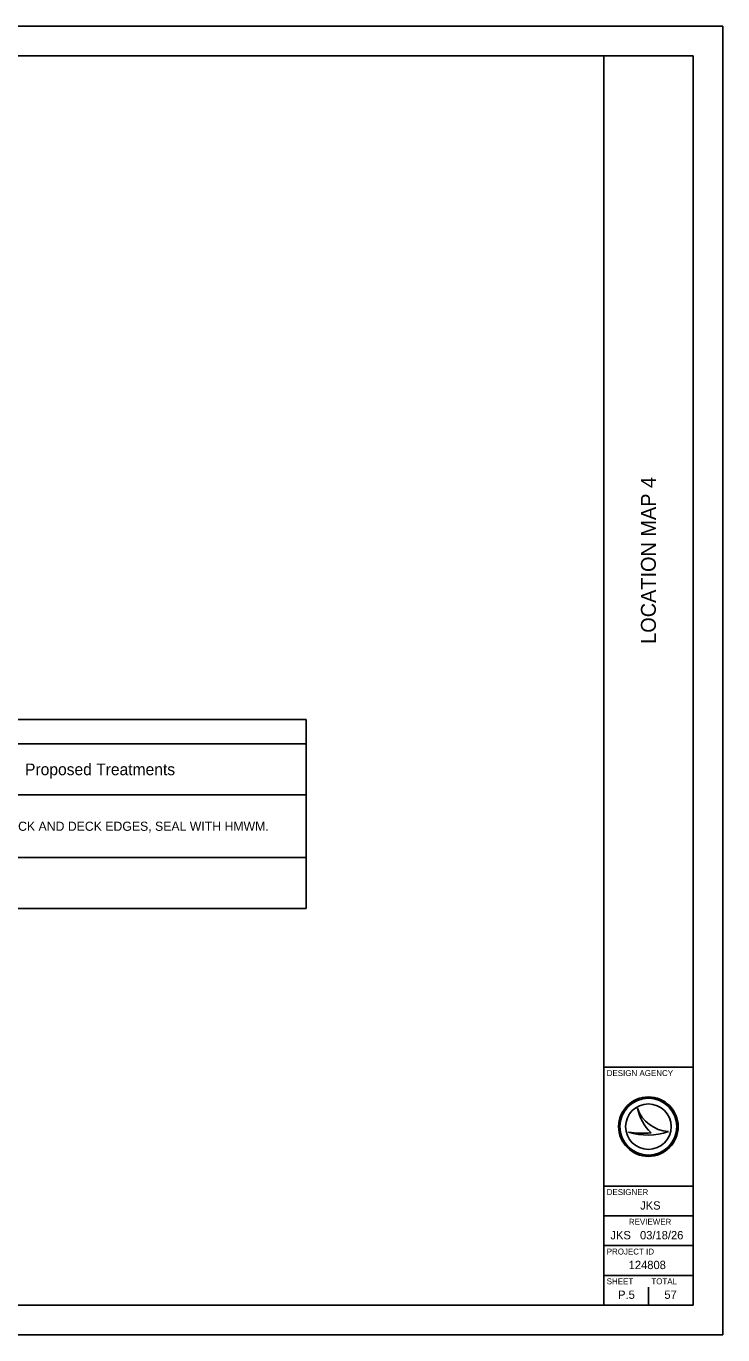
# Model space of a CAD drawing. Extents: x 0 to 34, y 0 to 22.
# Drawn here: x 22.3 to 34, y 0 to 22 of the extents above; entities that cross this region are included whole.
import ezdxf

# ---------------------------------------------------------------- set-up
doc = ezdxf.new("R2010")
doc.units = 0
for name, color, linetype in [('SH_Border', 7, 'Continuous'), ('SH_Cut_Line', 7, 'Continuous'), ('SH_Data', 7, 'Continuous'), ('SH_Text', 7, 'Continuous')]:
    doc.layers.add(name, color=color, linetype=linetype)

msp = doc.modelspace()

# ---------------------------------------------------------------- linework, layer by layer
at = {"layer": 'SH_Border'}
for p, q in [((32, 0.5), (32, 21.5)), ((32, 4.5), (33.5, 4.5)), ((32, 2.5), (33.5, 2.5)), ((32, 2), (33.5, 2)), ((32, 1.5), (33.5, 1.5)), ((32, 1), (33.5, 1))]:
    msp.add_line(p, q, dxfattribs=at)
msp.add_lwpolyline([(1.5, 21.5), (33.5, 21.5), (33.5, 0.5), (1.5, 0.5)], close=True, dxfattribs=at)
at = {"layer": 'SH_Cut_Line'}
msp.add_lwpolyline([(0, 0), (34, 0), (34, 22), (0, 22)], close=True, dxfattribs=at)
at = {"layer": 'SH_Data'}
for p, q in [((32.567, 3.81), (32.567, 3.81)), ((32.417, 3.41), (32.417, 3.41)), ((32.75, 3.5), (32.75, 3.5)), ((33.087, 3.419), (33.087, 3.419)), ((32.375, 0.675), (32.375, 0.675)), ((32.75, 0.5), (32.75, 0.8))]:
    msp.add_line(p, q, dxfattribs=at)
for radius in [0.5, 0.477, 0.477, 0.382]:
    msp.add_circle((32.75, 3.5), radius, dxfattribs=at)
for centre, radius, start, end in [((33.116, 3.998), 0.58, 198.9257, 198.9319), ((33.347, 3.97), 0.796, 191.6379, 191.6421), ((33.116, 3.998), 0.58, 198.9319, 267.1657), ((33.347, 3.97), 0.796, 191.6421, 226.0947), ((32.739, 4.37), 1.013, 251.4576, 290.0832), ((32.648, 4.654), 1.266, 259.4964, 259.4995), ((32.739, 4.37), 1.013, 251.4527, 251.4576), ((32.648, 4.654), 1.266, 259.4995, 276.6672)]:
    msp.add_arc(centre, radius, start, end, dxfattribs=at)
at = {"layer": 'SH_Text'}
for p, q in [((8.161, 10.346), (27.003, 10.346)), ((27.003, 10.346), (27.003, 7.167)), ((8.161, 9.934), (27.003, 9.934)), ((8.161, 9.077), (27.003, 9.077)), ((8.161, 8.023), (27.003, 8.023)), ((8.161, 7.167), (27.003, 7.167))]:
    msp.add_line(p, q, dxfattribs=at)

# ---------------------------------------------------------------- texts
at = {"layer": 'SH_Data'}
msp.add_text('LOCATION MAP 4', height=0.25, rotation=90, dxfattribs=at).set_placement((32.875, 11.617))
for s, height, p in [('DESIGN AGENCY', 0.1, (32.05, 4.35)), ('DESIGNER', 0.1, (32.05, 2.35)), ('JKS', 0.14, (32.612, 2.105)), ('REVIEWER', 0.1, (32.422, 1.85)), ('JKS', 0.14, (32.112, 1.605)), ('03/18/26', 0.14, (32.609, 1.605)), ('PROJECT ID', 0.1, (32.05, 1.35)), ('124808', 0.14, (32.419, 1.105)), ('SHEET', 0.1, (32.05, 0.85)), ('TOTAL', 0.1, (32.8, 0.85)), ('P.5', 0.14, (32.241, 0.605)), ('57', 0.14, (33.018, 0.605))]:
    msp.add_text(s, height=height, dxfattribs=at).set_placement(p)
at = {"layer": 'SH_Text'}
for s, height, p in [('Proposed Treatments', 0.196, (22.279, 9.408)), ('PATCH DECK AND DECK EDGES, SEAL WITH HMWM.', 0.154, (21.121, 8.473))]:
    msp.add_text(s, height=height, dxfattribs=at).set_placement(p)

doc.saveas('drawing.dxf')
